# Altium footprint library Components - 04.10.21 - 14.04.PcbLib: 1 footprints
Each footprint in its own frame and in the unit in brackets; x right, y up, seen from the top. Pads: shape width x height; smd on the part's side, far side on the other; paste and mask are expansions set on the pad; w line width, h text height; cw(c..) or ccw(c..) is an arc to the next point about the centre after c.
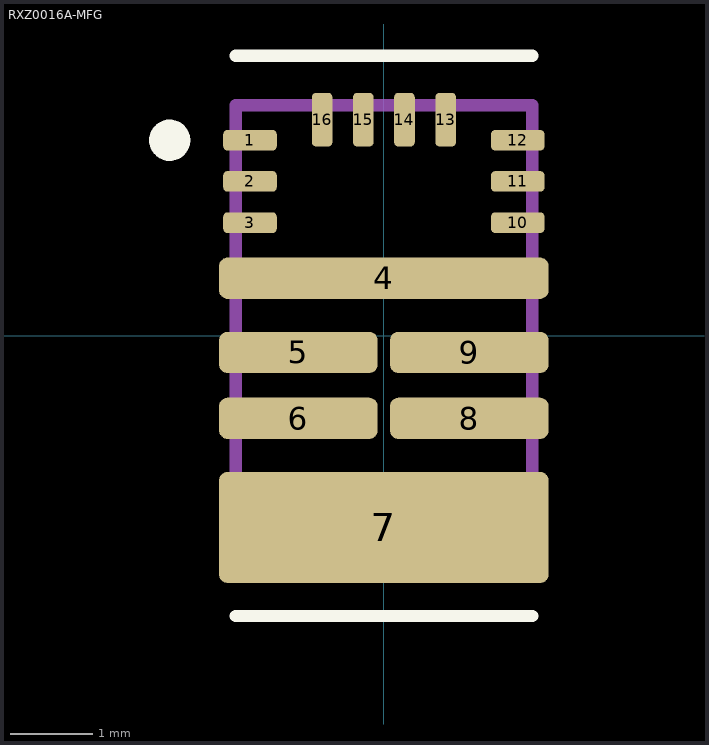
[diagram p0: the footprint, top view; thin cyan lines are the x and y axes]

## RXZ0016A-MFG [mm]
pads (16):
  rrect40% 0.65x0.25 smd paste+0 mask+0: 1(-1.625,2.375) 2(-1.625,1.875) 3(-1.625,1.375) 10(1.625,1.375) 11(1.625,1.875) 12(1.625,2.375)
  rrect40% 4x0.5 smd paste-1000 mask-1000: 4(0,0.7)
  rrect40% 1.925x0.5 smd paste-1000 mask-1000: 5(-1.038,-0.2) 6(-1.038,-1) 8(1.038,-1) 9(1.038,-0.2)
  rrect15% 4x1.35 smd paste-1000 mask-1000: 7(0,-2.325)
  rrect40% 0.25x0.65 smd paste+0 mask+0: 13(0.75,2.625) 14(0.25,2.625) 15(-0.25,2.625) 16(-0.75,2.625)
Top Overlay:
  circle w0.25: c-2.6,2.375 r0.125
  lines w0.15: -1.8,-3.4 1.8,-3.4 ; -1.8,3.4 1.8,3.4
Top Paste:
  drawing of 12 lines, arcs and shapes, not listed
Top Solder:
  drawing of 6 lines, arcs and shapes, not listed
Mechanical 5:
  lines w0.15: -1.8,-2.8 -1.8,2.8 1.8,2.8 1.8,-2.8 -1.8,-2.8
  text ".Designator" at 0,-0.025 h0.5
3D body "IC_DRV8245_VQFN_HR_VQFNHR16.STEP": height 0.25, standoff 0, extent -2.1,-3.1 2.1,3.05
